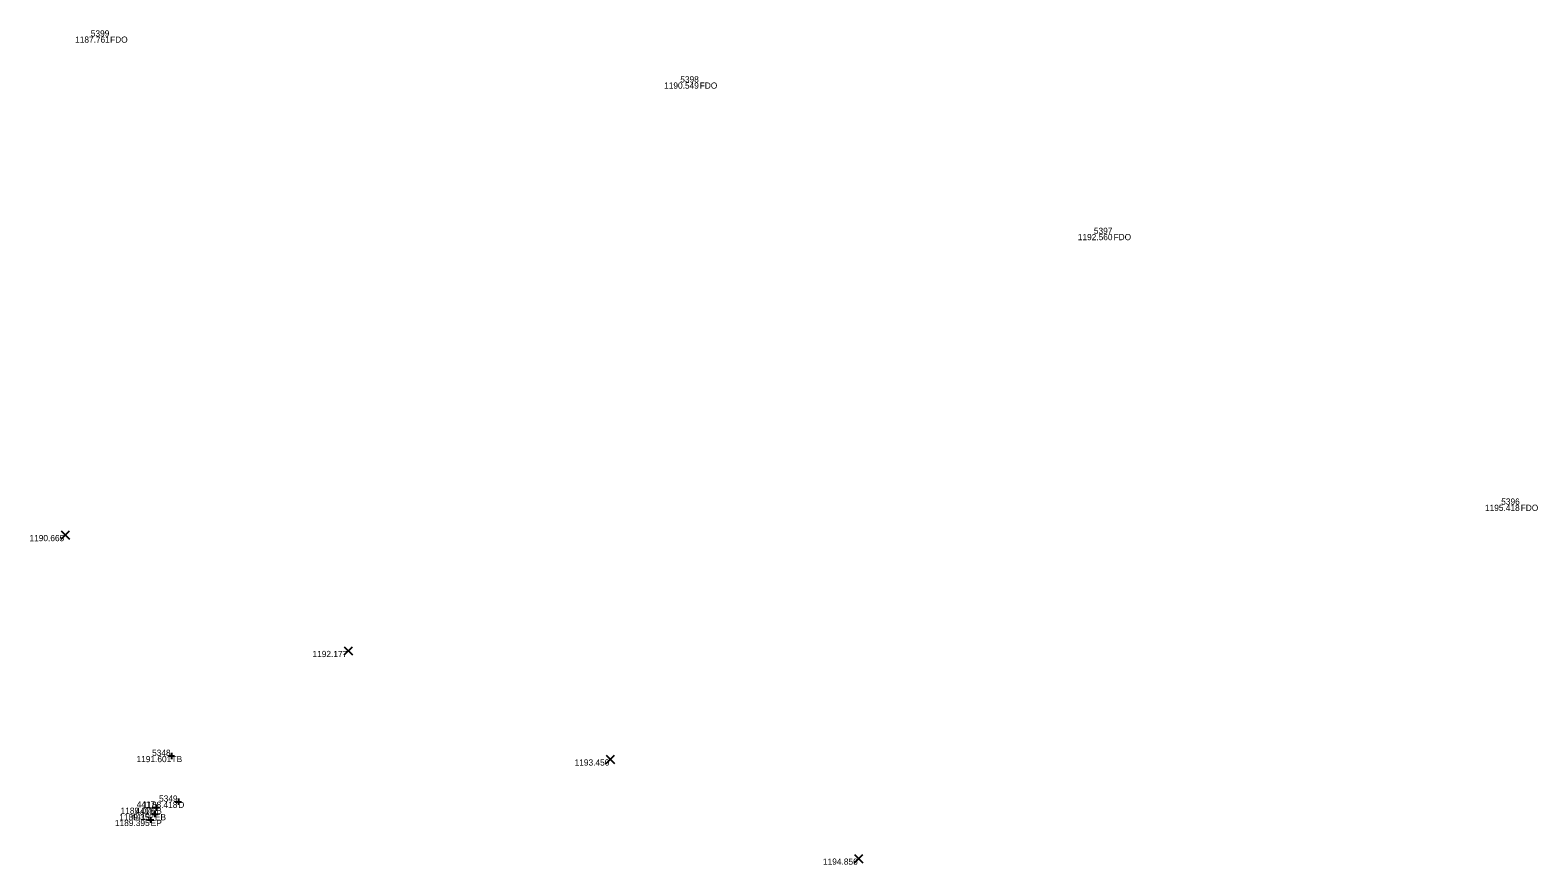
# Model space of a CAD drawing. Extents: x 2044997 to 2050342, y 455233 to 458054.
# Drawn here: x 2047208.3 to 2047450.6, y 457152.8 to 457286.8 of the extents above; entities that cross this region are included whole.
import ezdxf

# ---------------------------------------------------------------- set-up
doc = ezdxf.new("R2010")
doc.units = 0
for name, color, linetype in [('SV_X_Random_Point', 7, 'Continuous'), ('SV_X_Shot_Marker', 7, 'Continuous'), ('SV_X_Text_Comment', 7, 'Continuous'), ('SV_X_Text_Elevation', 7, 'Continuous'), ('SV_X_Text_Name', 7, 'Continuous')]:
    doc.layers.add(name, color=color, linetype=linetype)

msp = doc.modelspace()

# ---------------------------------------------------------------- linework, layer by layer
at = {"layer": 'SV_X_Random_Point'}
for p, q in [((2047213.32, 457205.08), (2047214.65, 457206.42)), ((2047213.32, 457206.42), (2047214.65, 457205.08)), ((2047258.83, 457186.48), (2047260.16, 457187.81)), ((2047258.83, 457187.81), (2047260.16, 457186.48)), ((2047300.91, 457169.05), (2047302.24, 457170.38)), ((2047300.91, 457170.38), (2047302.24, 457169.05)), ((2047340.82, 457153.13), (2047342.16, 457154.47)), ((2047340.82, 457154.47), (2047342.16, 457153.13))]:
    msp.add_line(p, q, dxfattribs=at)
at = {"layer": 'SV_X_Shot_Marker'}
for p, q in [((2047230.56, 457170.27), (2047231.56, 457170.27)), ((2047231.06, 457170.77), (2047231.06, 457169.77)), ((2047231.06, 457170.27), (2047231.06, 457170.27)), ((2047228.12, 457161.97), (2047229.12, 457161.97)), ((2047228.62, 457162.47), (2047228.62, 457161.47)), ((2047228.62, 457161.97), (2047228.62, 457161.97)), ((2047231.66, 457162.92), (2047232.66, 457162.92)), ((2047232.16, 457163.42), (2047232.16, 457162.42)), ((2047232.16, 457162.92), (2047232.16, 457162.92)), ((2047227.21, 457160.01), (2047228.21, 457160.01)), ((2047227.71, 457160.51), (2047227.71, 457159.51)), ((2047227.71, 457160.01), (2047227.71, 457160.01)), ((2047227.89, 457160.94), (2047228.89, 457160.94)), ((2047228.39, 457161.44), (2047228.39, 457160.44)), ((2047228.39, 457160.94), (2047228.39, 457160.94))]:
    msp.add_line(p, q, dxfattribs=at)

# ---------------------------------------------------------------- texts
at = {"layer": 'SV_X_Text_Comment'}
for s, p in [('FDO', (2047221.19, 457284.78)), ('FDO', (2047315.94, 457277.4)), ('FDO', (2047382.44, 457253.08)), ('FDO', (2047447.87, 457209.61)), ('TB', (2047231.06, 457169.27)), ('B', (2047228.62, 457160.97)), ('D', (2047232.16, 457161.92)), ('EP', (2047227.71, 457159.01)), ('EB', (2047228.39, 457159.94))]:
    msp.add_text(s, height=1, dxfattribs=at).set_placement(p)
at = {"layer": 'SV_X_Text_Elevation'}
for s, p in [('1187.761', (2047215.57, 457284.78)), ('1190.549', (2047310.22, 457277.4)), ('1192.560', (2047376.7, 457253.08)), ('1195.418', (2047442.13, 457209.61)), ('1190.665', (2047208.24, 457204.75)), ('1192.177', (2047253.72, 457186.14)), ('1191.601', (2047225.44, 457169.27)), ('1193.450', (2047295.84, 457168.72)), ('1189.076', (2047222.88, 457160.97)), ('1188.418', (2047226.43, 457161.92)), ('1189.395', (2047221.97, 457159.01)), ('1189.352', (2047222.66, 457159.94)), ('1194.856', (2047335.75, 457152.8))]:
    msp.add_text(s, height=1, dxfattribs=at).set_placement(p)
at = {"layer": 'SV_X_Text_Name'}
for s, p in [('5399', (2047218.09, 457285.78)), ('5398', (2047312.82, 457278.4)), ('5397', (2047379.28, 457254.08)), ('5396', (2047444.74, 457210.61)), ('5348', (2047227.94, 457170.27)), ('4418', (2047225.27, 457160.94)), ('4417', (2047225.46, 457161.97)), ('5349', (2047229.06, 457162.92)), ('4419', (2047224.61, 457160.01))]:
    msp.add_text(s, height=1, dxfattribs=at).set_placement(p)

doc.saveas('drawing.dxf')
